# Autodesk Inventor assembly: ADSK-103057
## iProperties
Shininess: 0.0
Created: 2000-11
Part Number: ADSK-103057
Document SubType Name: Assembly
Stock Number: ADSK-103057
Density: 0.0
Volumn: 0.0
Area: 0.0
PropertySet Name: Model Information
Control State: 0
Master: False
Checked Out: False
Author: gao
